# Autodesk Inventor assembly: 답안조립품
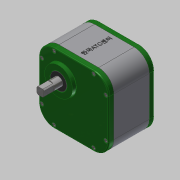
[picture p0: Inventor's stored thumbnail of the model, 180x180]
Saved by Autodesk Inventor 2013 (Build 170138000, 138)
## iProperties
Created: 2017-11
Part Number: 답안조립품
Document SubType Name: Assembly
Designer: Administrator
Author: Administrator
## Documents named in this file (11)
- C:\Users\Administrator\Desktop\371108V1025\답안조립품.iam
- C:\Users\Administrator\Desktop\371108V1025\본체.ipt
- C:\Users\Administrator\Desktop\371108V1025\뒤커버.ipt
- C:\Users\Administrator\Desktop\371108V1025\메인축.ipt
- C:\Users\Administrator\Desktop\371108V1025\베어링 608.ipt
- C:\Users\Administrator\Desktop\371108V1025\베어링 6003.ipt
- C:\Users\Administrator\Desktop\371108V1025\볼트 M4.ipt
- C:\Users\Administrator\Desktop\371108V1025\서브축.ipt
- C:\Users\Administrator\Desktop\371108V1025\앞커버.ipt
- C:\Users\Administrator\Desktop\371108V1025\오일실 8 22 7.ipt
- C:\Users\Administrator\Desktop\371108V1025\오일실 17 32 8.ipt
